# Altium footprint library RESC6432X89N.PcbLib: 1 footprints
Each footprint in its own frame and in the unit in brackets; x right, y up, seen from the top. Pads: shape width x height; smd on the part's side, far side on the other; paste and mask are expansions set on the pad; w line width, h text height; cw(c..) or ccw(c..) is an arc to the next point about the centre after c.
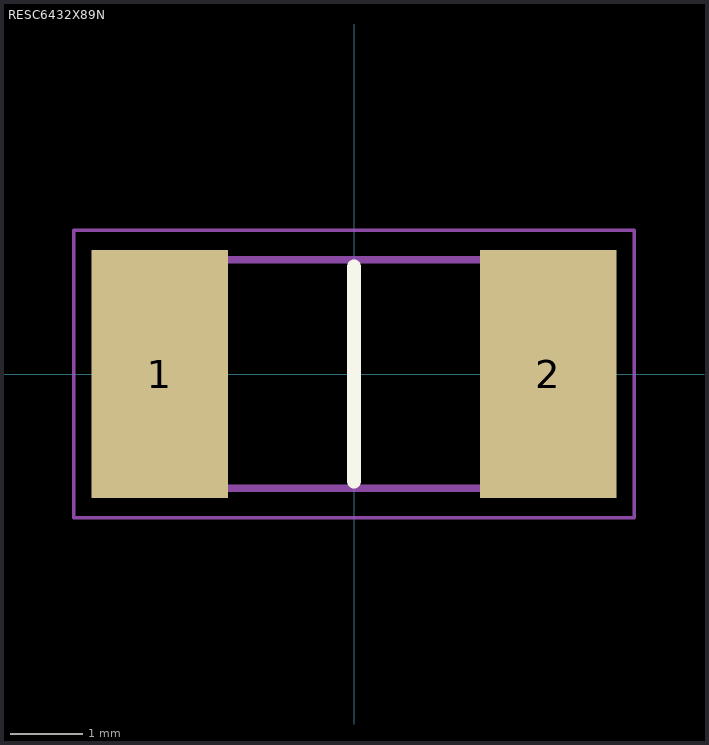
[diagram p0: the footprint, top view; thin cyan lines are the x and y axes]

## RESC6432X89N [mm]
pads (2):
  rect 1.9x3.45 smd: 1(-2.7,0) 2(2.7,0)
Top Overlay:
  lines w0.2: 0,-1.49 0,1.49
Mechanical 15:
  lines w0.1: -3.175,-1.59 3.175,-1.59 3.175,1.59 -3.175,1.59 -3.175,-1.59
Mechanical 20:
  lines w0.05: -3.9,-2 3.9,-2 3.9,2 -3.9,2 -3.9,-2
